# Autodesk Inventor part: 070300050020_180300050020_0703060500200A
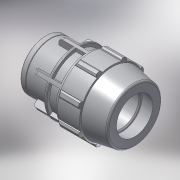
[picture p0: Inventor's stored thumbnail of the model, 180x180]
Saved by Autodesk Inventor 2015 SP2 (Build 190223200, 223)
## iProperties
Created: 2017-02
Part Number: 070300050020_180300050020_0703060500200A
Material: PVC-Piping
Description: PLASSON FEMALE ADAPTOR 50-2"
Document SubType Name: Modeling
Designer: KIM
Mass: 92.6774 g
Surface Area: 199.44 cm^2
Volume: 66.1981 cm^3
Density: 1.4 g/cm^3
Appearance: Smooth - White
Author: KIM
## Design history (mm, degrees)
derived "07030.ipt"
feature "Solid1::07030.ipt"
tag "TaggingFeature1"
body "Solid1"
other parameters: "d4" = 18.28571, "d5" = 32, "d7" = 96, "d9" = 18.28571, "d11" = 3.65714, "d12" = 76.8, "d13" = 120 deg, "d14" = 75, "d15" = 10 deg, "d16" = 86.4, "d18" = 2.5, "d19" = 35 deg, "d20" = 17.5 deg, "d21" = 89.28, "d23" = 0, "d25" = 360 deg, "d27" = 1.92, "d34" = 4.8, "d35" = 38.4, "d36" = 0, "d42" = 32, "d43" = 2.88, "d46" = 1.5, "d49" = 93, "d51" = 128, "d53" = 1, "d55" = 360 deg, "d63" = 56.656, "d64" = 42.66667, "d65" = 4.8, "d66" = 0.5, "d67" = 1, "d68" = 9, "d69" = 69.12, "d70" = 2.4, "E_" = 96, "H_" = 128, "l_" = 93, "Rp_" = 56.656
